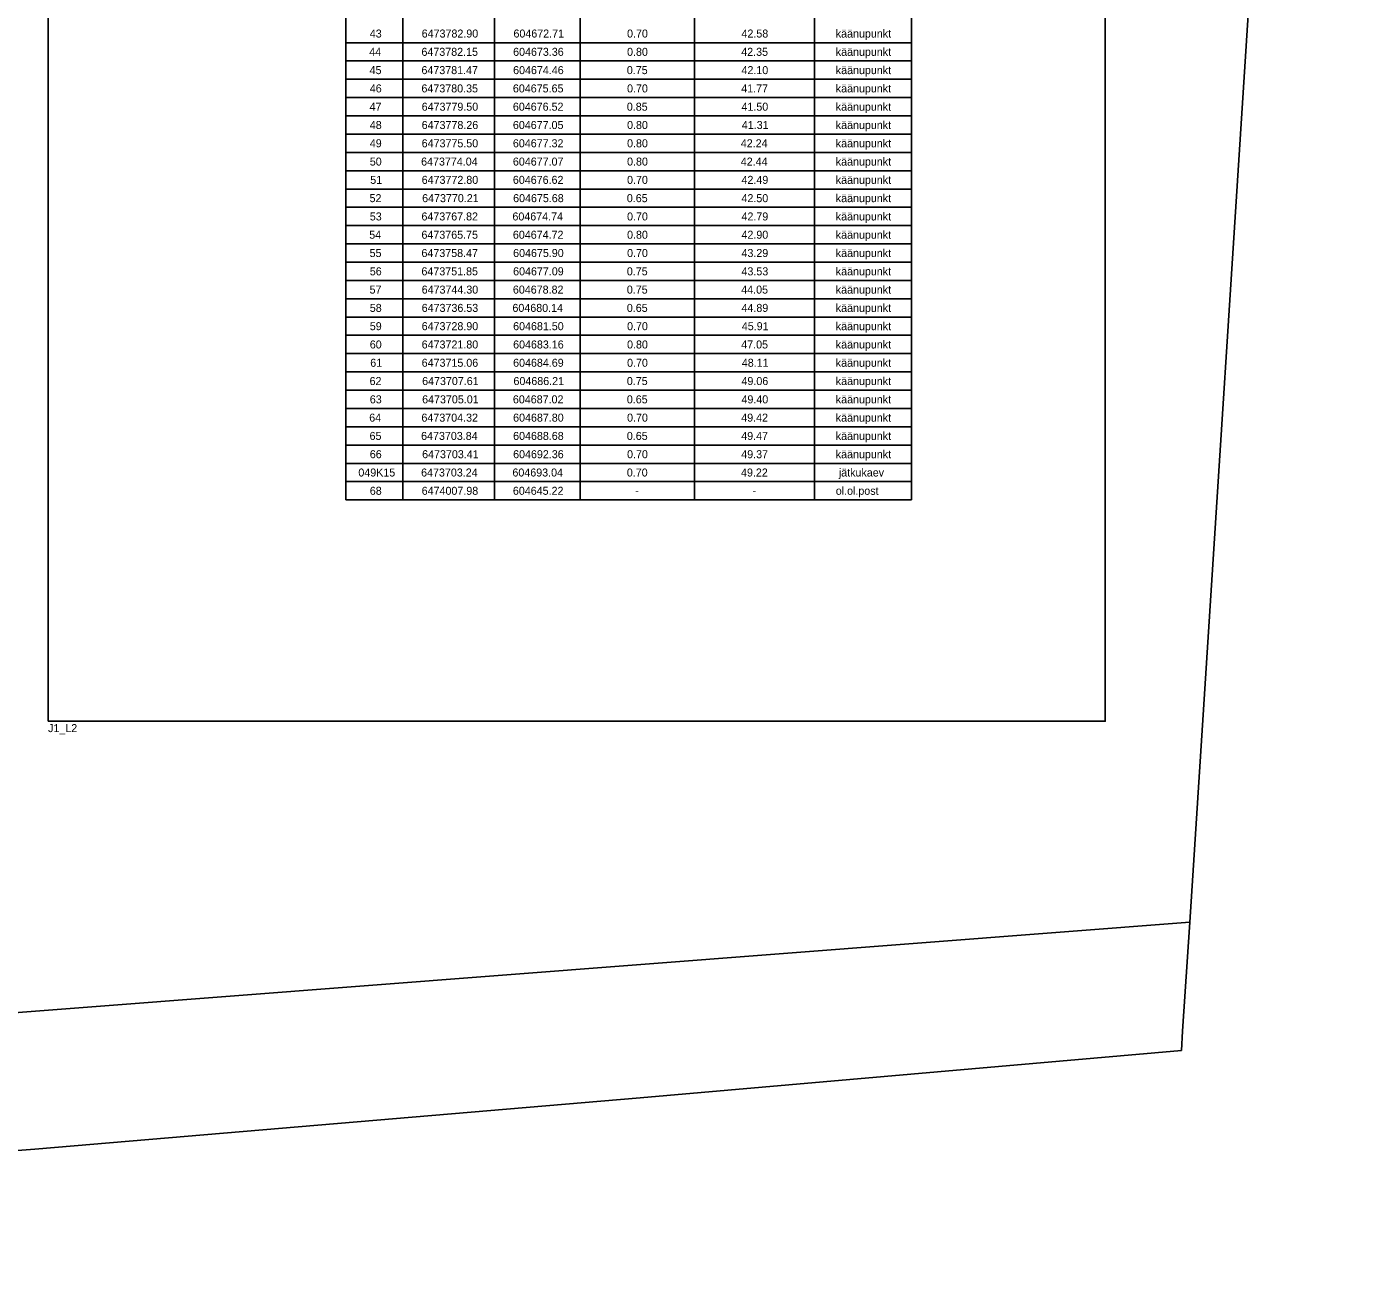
# Model space of a CAD drawing. Extents: x 604066 to 604956, y 6473634 to 6474346.
# Drawn here: x 604839 to 604956.1, y 6473693.4 to 6473802.4 of the extents above; entities that cross this region are included whole.
import ezdxf

# ---------------------------------------------------------------- set-up
doc = ezdxf.new("R2010")
doc.units = 0
for name, color, linetype in [('ABIJOONIS', 7, 'Continuous'), ('PIIR', 7, 'Continuous'), ('VORMISTUS', 7, 'Continuous')]:
    doc.layers.add(name, color=color, linetype=linetype)

msp = doc.modelspace()

# ---------------------------------------------------------------- linework, layer by layer
at = {"layer": 'ABIJOONIS'}
for p, q in [((604866.96, 6473874.79), (604866.96, 6473760.99)), ((604871.96, 6473874.79), (604871.96, 6473760.99)), ((604887.46, 6473874.79), (604887.46, 6473760.99)), ((604897.46, 6473874.79), (604897.46, 6473760.99)), ((604907.96, 6473874.79), (604907.96, 6473760.99)), ((604916.46, 6473874.79), (604916.46, 6473760.99)), ((604879.96, 6473871.54), (604879.96, 6473760.99)), ((604866.96, 6473800.99), (604916.46, 6473800.99)), ((604866.96, 6473799.39), (604916.46, 6473799.39)), ((604866.96, 6473797.79), (604916.46, 6473797.79)), ((604866.96, 6473796.19), (604916.46, 6473796.19)), ((604866.96, 6473794.59), (604916.46, 6473794.59)), ((604866.96, 6473792.99), (604916.46, 6473792.99)), ((604866.96, 6473791.39), (604916.46, 6473791.39)), ((604866.96, 6473789.79), (604916.46, 6473789.79)), ((604866.96, 6473788.19), (604916.46, 6473788.19)), ((604866.96, 6473786.59), (604916.46, 6473786.59)), ((604866.96, 6473784.99), (604916.46, 6473784.99)), ((604866.96, 6473783.39), (604916.46, 6473783.39)), ((604866.96, 6473781.79), (604916.46, 6473781.79)), ((604866.96, 6473780.19), (604916.46, 6473780.19)), ((604866.96, 6473778.59), (604916.46, 6473778.59)), ((604866.96, 6473776.99), (604916.46, 6473776.99)), ((604866.96, 6473775.39), (604916.46, 6473775.39)), ((604866.96, 6473773.79), (604916.46, 6473773.79)), ((604866.96, 6473772.19), (604916.46, 6473772.19)), ((604866.96, 6473770.59), (604916.46, 6473770.59)), ((604866.96, 6473768.99), (604916.46, 6473768.99)), ((604866.96, 6473767.39), (604916.46, 6473767.39)), ((604866.96, 6473765.79), (604916.46, 6473765.79)), ((604866.96, 6473764.19), (604916.46, 6473764.19)), ((604866.96, 6473762.59), (604916.46, 6473762.59)), ((604866.96, 6473760.99), (604916.46, 6473760.99))]:
    msp.add_line(p, q, dxfattribs=at)
at = {"layer": 'PIIR'}
for points in [[(604833.54, 6473909.5), (604897.39, 6473936.49), (604953.49, 6473960.24), (604956.07, 6473961.29), (604940.8, 6473724.06), (604687.73, 6473704.56), (604680.66, 6473747.8), (604821.94, 6473844.68)], [(604687.73, 6473704.56), (604940.8, 6473724.06), (604940.18, 6473714.53), (604940.07, 6473712.83), (604892.72, 6473708.69), (604839.74, 6473704.2), (604787.09, 6473700.12), (604735.18, 6473696.42), (604689.63, 6473693.43), (604689.38, 6473694.91)]]:
    msp.add_lwpolyline(points, close=True, dxfattribs=at)
at = {"layer": 'VORMISTUS'}
msp.add_lwpolyline([(604840.91, 6473741.63), (604840.91, 6473885.13), (604933.41, 6473885.13), (604933.41, 6473741.63)], close=True, dxfattribs=at)

# ---------------------------------------------------------------- texts
at = {"layer": 'ABIJOONIS'}
for s, p in [('43', (604869.06, 6473801.44)), ('6473782.90', (604873.6, 6473801.44)), ('604672.71', (604881.63, 6473801.44)), ('0.70', (604891.57, 6473801.44)), ('42.58', (604901.58, 6473801.44)), ('käänupunkt', (604909.83, 6473801.44)), ('44', (604869.01, 6473799.84)), ('6473782.15', (604873.58, 6473799.84)), ('604673.36', (604881.6, 6473799.84)), ('0.80', (604891.57, 6473799.84)), ('42.35', (604901.56, 6473799.84)), ('käänupunkt', (604909.83, 6473799.84)), ('45', (604869.04, 6473798.24)), ('6473781.47', (604873.58, 6473798.24)), ('604674.46', (604881.6, 6473798.24)), ('0.75', (604891.55, 6473798.24)), ('42.10', (604901.58, 6473798.24)), ('käänupunkt', (604909.83, 6473798.24)), ('46', (604869.06, 6473796.64)), ('6473780.35', (604873.58, 6473796.64)), ('604675.65', (604881.58, 6473796.64)), ('0.70', (604891.57, 6473796.64)), ('41.77', (604901.56, 6473796.64)), ('käänupunkt', (604909.83, 6473796.64)), ('47', (604869.04, 6473795.04)), ('6473779.50', (604873.6, 6473795.04)), ('604676.52', (604881.58, 6473795.04)), ('0.85', (604891.55, 6473795.04)), ('41.50', (604901.58, 6473795.04)), ('käänupunkt', (604909.83, 6473795.04)), ('48', (604869.06, 6473793.44)), ('6473778.26', (604873.6, 6473793.44)), ('604677.05', (604881.58, 6473793.44)), ('0.80', (604891.57, 6473793.44)), ('41.31', (604901.61, 6473793.44)), ('käänupunkt', (604909.83, 6473793.44)), ('49', (604869.06, 6473791.84)), ('6473775.50', (604873.6, 6473791.84)), ('604677.32', (604881.58, 6473791.84)), ('0.80', (604891.57, 6473791.84)), ('42.24', (604901.52, 6473791.84)), ('käänupunkt', (604909.83, 6473791.84)), ('50', (604869.06, 6473790.24)), ('6473774.04', (604873.55, 6473790.24)), ('604677.07', (604881.58, 6473790.24)), ('0.80', (604891.57, 6473790.24)), ('42.44', (604901.52, 6473790.24)), ('käänupunkt', (604909.83, 6473790.24)), ('51', (604869.1, 6473788.64)), ('6473772.80', (604873.6, 6473788.64)), ('604676.62', (604881.58, 6473788.64)), ('0.70', (604891.57, 6473788.64)), ('42.49', (604901.58, 6473788.64)), ('käänupunkt', (604909.83, 6473788.64)), ('52', (604869.04, 6473787.04)), ('6473770.21', (604873.64, 6473787.04)), ('604675.68', (604881.6, 6473787.04)), ('0.65', (604891.55, 6473787.04)), ('42.50', (604901.58, 6473787.04)), ('käänupunkt', (604909.83, 6473787.04)), ('käänupunkt', (604909.83, 6473785.44)), ('53', (604869.06, 6473785.44)), ('6473767.82', (604873.58, 6473785.44)), ('604674.74', (604881.54, 6473785.44)), ('0.70', (604891.57, 6473785.44)), ('42.79', (604901.58, 6473785.44)), ('54', (604869.01, 6473783.84)), ('6473765.75', (604873.58, 6473783.84)), ('604674.72', (604881.58, 6473783.84)), ('0.80', (604891.57, 6473783.84)), ('42.90', (604901.58, 6473783.84)), ('käänupunkt', (604909.83, 6473783.84)), ('55', (604869.04, 6473782.24)), ('6473758.47', (604873.58, 6473782.24)), ('604675.90', (604881.6, 6473782.24)), ('0.70', (604891.57, 6473782.24)), ('43.29', (604901.58, 6473782.24)), ('käänupunkt', (604909.83, 6473782.24)), ('56', (604869.06, 6473780.64)), ('6473751.85', (604873.58, 6473780.64)), ('604677.09', (604881.6, 6473780.64)), ('0.75', (604891.55, 6473780.64)), ('43.53', (604901.58, 6473780.64)), ('käänupunkt', (604909.83, 6473780.64)), ('57', (604869.04, 6473779.04)), ('6473744.30', (604873.6, 6473779.04)), ('604678.82', (604881.58, 6473779.04)), ('0.75', (604891.55, 6473779.04)), ('44.05', (604901.56, 6473779.04)), ('käänupunkt', (604909.83, 6473779.04)), ('58', (604869.06, 6473777.44)), ('6473736.53', (604873.6, 6473777.44)), ('604680.14', (604881.54, 6473777.44)), ('0.65', (604891.55, 6473777.44)), ('44.89', (604901.58, 6473777.44)), ('käänupunkt', (604909.83, 6473777.44)), ('59', (604869.06, 6473775.84)), ('6473728.90', (604873.6, 6473775.84)), ('604681.50', (604881.6, 6473775.84)), ('0.70', (604891.57, 6473775.84)), ('45.91', (604901.61, 6473775.84)), ('käänupunkt', (604909.83, 6473775.84)), ('60', (604869.06, 6473774.24)), ('6473721.80', (604873.6, 6473774.24)), ('604683.16', (604881.6, 6473774.24)), ('0.80', (604891.57, 6473774.24)), ('47.05', (604901.56, 6473774.24)), ('käänupunkt', (604909.83, 6473774.24)), ('61', (604869.1, 6473772.64)), ('6473715.06', (604873.6, 6473772.64)), ('604684.69', (604881.6, 6473772.64)), ('0.70', (604891.57, 6473772.64)), ('48.11', (604901.61, 6473772.64)), ('käänupunkt', (604909.83, 6473772.64)), ('62', (604869.04, 6473771.04)), ('6473707.61', (604873.64, 6473771.04)), ('604686.21', (604881.63, 6473771.04)), ('0.75', (604891.55, 6473771.04)), ('49.06', (604901.58, 6473771.04)), ('käänupunkt', (604909.83, 6473771.04)), ('63', (604869.06, 6473769.44)), ('6473705.01', (604873.64, 6473769.44)), ('604687.02', (604881.58, 6473769.44)), ('0.65', (604891.55, 6473769.44)), ('49.40', (604901.58, 6473769.44)), ('käänupunkt', (604909.83, 6473769.44)), ('64', (604869.01, 6473767.84)), ('6473704.32', (604873.58, 6473767.84)), ('604687.80', (604881.6, 6473767.84)), ('0.70', (604891.57, 6473767.84)), ('49.42', (604901.56, 6473767.84)), ('käänupunkt', (604909.83, 6473767.84)), ('65', (604869.04, 6473766.24)), ('6473703.84', (604873.55, 6473766.24)), ('604688.68', (604881.6, 6473766.24)), ('0.65', (604891.55, 6473766.24)), ('49.47', (604901.56, 6473766.24)), ('käänupunkt', (604909.83, 6473766.24)), ('66', (604869.06, 6473764.64)), ('6473703.41', (604873.64, 6473764.64)), ('604692.36', (604881.6, 6473764.64)), ('0.70', (604891.57, 6473764.64)), ('49.37', (604901.56, 6473764.64)), ('käänupunkt', (604909.83, 6473764.64)), ('049K15', (604868.06, 6473763.04)), ('6473703.24', (604873.55, 6473763.04)), ('604693.04', (604881.54, 6473763.04)), ('0.70', (604891.55, 6473763.04)), ('49.22', (604901.54, 6473763.04)), ('jätkukaev', (604910.1, 6473763.04)), ('68', (604869.06, 6473761.44)), ('6474007.98', (604873.6, 6473761.44)), ('604645.22', (604881.58, 6473761.44)), ('-', (604892.29, 6473761.44)), ('-', (604902.54, 6473761.44)), ('ol.ol.post', (604909.83, 6473761.44))]:
    msp.add_text(s, height=0.7, dxfattribs=at).set_placement(p)
at = {"layer": 'VORMISTUS'}
msp.add_text('J1_L2', height=0.7, dxfattribs=at).set_placement((604840.91, 6473740.68))

doc.saveas('drawing.dxf')
